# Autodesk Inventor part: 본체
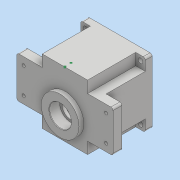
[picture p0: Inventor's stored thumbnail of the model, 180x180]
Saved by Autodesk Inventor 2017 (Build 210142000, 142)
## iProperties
Part Number: 본체
Material: 일반
Document SubType Name: Modeling
Designer: user
Density: 1 g/cm^3
Appearance: 기본값
Author: user
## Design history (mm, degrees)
sketch "스케치1"
  geometry: L1 (0, -94)-(-33, -94); L2 (-33, -94)-(-33, -77); L3 (-33, -77)-(-70, -77); L4 (-70, -77)-(-70, -17); L5 (-70, -17)-(-33, -17); L6 (-33, -17)-(-33, 0); L7 (-33, 0)-(0, 0); L8 (0, -94)-(0, 0); L9 (0, -94)-(33, -94); L10 (33, -94)-(33, -77); L11 (33, -77)-(70, -77); L12 (70, -77)-(70, -17); L13 (70, -17)-(33, -17); L14 (33, -17)-(33, 0); L15 (33, 0)-(0, 0)
  constraints: 30 end point, 6 perpendicular, 6 symmetric about line, 2 horizontal
  dimensions: "d0" = 94 distance between parallel lines of L7 L1; "d1" = 33 distance from line of L7.end L2; "d2" = 70 distance from line of L7.end L4; "d3" = 33 distance from line of L7.end L6; "d4" = 60 distance between parallel lines of L5 L3; "d5" = 17 distance between parallel lines of L3 L1
extrude "돌출1" new body sketch "스케치1" distance "d6" = 13; taper "d7" = 0 deg
sketch "스케치3"
  geometry: L1 (-33, 0)-(33, 0) reference; L2 (33, 94)-(-33, 94) reference; L3 (-33, 94)-(33, 94); L4 (33, 77)-(33, 94) reference; L5 (33, 94)-(33, 77); L6 (33, 77)-(47, 77); L7 (70, 77)-(33, 77) reference; L8 (47, 77)-(47, 17); L9 (33, 17)-(70, 17) reference; L10 (33, 17)-(33, 0); L11 (33, 0)-(0, 0); L12 (-33, 17)-(-33, 0) reference; L13 (-33, 0)-(-33, 17); L14 (-33, 17)-(-47, 17); L15 (-70, 17)-(-33, 17) reference; L16 (-33, 77)-(-70, 77) reference; L17 (-47, 77)-(-33, 77); L18 (-33, 94)-(-33, 77) reference; L19 (-33, 77)-(-33, 94); L20 (-47, 77)-(-47, 17); L21 (0, 0)-(-33, 0); L22 (47, 17)-(33, 17)
  constraints: 26 end point, 4 collinear, 3 perpendicular, 3 point on line, 3 vertical, 1 horizontal
  dimensions: "d13" = 47 horizontal distance of L6.end L11.end; "d15" = 47 distance from line of L20 L11.end
extrude "돌출3" join sketch "스케치3" distance "d16" = 57; taper "d17" = 0 deg
sketch "스케치4"
  geometry: L1 (-47, 94)-(47, 94); L2 (47, 94)-(47, 0); L3 (47, 0)-(-47, 0); L4 (-47, 0)-(-47, 94); L5 (33, 94)-(-33, 94) reference; 2 further points
  constraints: 8 end point, 2 midpoint, 2 parallel, 1 horizontal, 1 perpendicular
  dimensions: "d18" = 94 distance of L2.end L3.end; "d19" = 94 distance of L1.end L2.end; "d20" = 47 distance from line of L4 point (0, 0)
extrude "돌출4" join sketch "스케치4" distance "d21" = 10; taper "d22" = 0 deg
sketch "스케치6"
  geometry: L1 (47, 94)-(-47, 94) reference; L2 (-47, 94)-(-47, 0) reference; C1 r 3.5 at (-40, 87); 1 further point
  constraints: 1 centre point
  dimensions: "d27" = 7 diameter of C1; "d28" = 7 distance from line of L1 C1.centre; "d29" = 7 distance from line of L2 C1.centre
extrude "돌출5" cut sketch "스케치6" distance "d30" = 30; taper "d31" = 0 deg
sketch "스케치8"
  geometry: 1 further point
sketch "스케치11"
  geometry: L1 (47, 94)-(-47, 94) reference; L2 (-47, 0)-(47, 0) reference; C1 r 43 at (0, 47); 2 further points
  constraints: 1 centre point, 1 midpoint, 1 vertical alignment
  dimensions: "d51" = 86 diameter of C1; "d52" = 47 distance from line of L1 C1.centre
extrude "돌출9" cut sketch "스케치11" distance "d53" = 9; taper "d54" = 0 deg
sketch "스케치12"
  geometry: C1 r 40 at (0, 0); C2 r 43 at (0, 0) reference; 1 further point
  constraints: 1 centre point, 1 concentric
  dimensions: "d55" = 80 diameter of C1
extrude "돌출10" cut sketch "스케치12" distance "d56" = 62; taper "d57" = 0 deg
sketch "스케치13"
  geometry: 1 further point
sketch "스케치14"
  geometry: C1 r 21 at (0, 11); C2 r 15 at (0, -20); C3 r 40 at (0, 0) reference; 1 further point
  constraints: 2 centre point, 2 vertical alignment
  dimensions: "d58" = 42 diameter of C1; "d59" = 30 diameter of C2; "d60" = 11 distance of C3.centre C1.centre; "d61" = 20 distance of C2.centre C3.centre
extrude "돌출11" join sketch "스케치14" distance "d62" = 7; taper "d63" = 0 deg
sketch "스케치15"
  geometry: L1 (-33, 0)-(33, 0) reference; L2 (-33, -17)-(-33, 0) reference; L3 (-70, -17)-(-33, -17) reference; L4 (-70, -77)-(-70, -17) reference; L5 (-33, -77)-(-70, -77) reference; L6 (-33, -94)-(-33, -77) reference; L7 (33, -94)-(-33, -94) reference; L8 (33, -77)-(33, -94) reference; L9 (70, -77)-(33, -77) reference; L10 (70, -17)-(70, -77) reference; L11 (33, -17)-(70, -17) reference; L12 (33, 0)-(33, -17) reference; C1 r 16 at (0, -58); C2 r 40 at (0, -47) reference; 1 further point
  constraints: 1 centre point, 1 vertical alignment
  dimensions: "d64" = 32 diameter of C1; "d65" = 11 distance of C2.centre C1.centre
extrude "돌출12" cut sketch "스케치15" distance "d66" = 8.3; taper "d67" = 0 deg
sketch "스케치16"
  geometry: C1 r 12.5 at (0, 0); C2 r 16 at (0, 0) reference; 1 further point
  constraints: 1 centre point, 1 concentric
  dimensions: "d68" = 25 diameter of C1
extrude "돌출13" cut sketch "스케치16" distance "d69" = 4.7; taper "d70" = 0 deg
sketch "스케치17"
  geometry: L1 (47, -19)-(47, 41) reference; C1 r 17.5 at (0, 0); A1 r 21 centre (0, 0) between (-8.978, 18.984) and (8.978, 18.984) reference; 1 further point
  constraints: 1 centre point, 1 concentric
  dimensions: "d71" = 35 diameter of C1
extrude "돌출14" cut sketch "스케치17" distance "d72" = 10; taper "d73" = 0 deg
sketch "스케치18"
  geometry: C1 r 11 at (0, -20); A1 r 15 centre (0, -20) between (-8.978, -7.984) and (8.978, -7.984) reference; 1 further point
  constraints: 1 centre point, 1 concentric
  dimensions: "d74" = 22 diameter of C1
extrude "돌출15" cut sketch "스케치18" distance "d75" = 7; taper "d76" = 0 deg
sketch "스케치19"
  geometry: C1 r 9.5 at (0, 0); C2 r 11 at (0, 0) reference; 1 further point
  constraints: 1 centre point, 1 concentric
  dimensions: "d77" = 19 diameter of C1
extrude "돌출16" cut sketch "스케치19" distance "d78" = 3; taper "d79" = 0 deg
sketch "스케치20"
  geometry: L1 (-14, 80)-(80, 80) reference; L2 (0, 0)-(66, 0) reference; 3 further points
  constraints: 1 midpoint, 1 vertical alignment, 1 other
  dimensions: "d81" = 40 distance from line of L1 point (33, 40)
feature "엠보싱2" sketch "스케치20" dims "d0" = 94, "d1" = 33, "d2" = 70, "d3" = 33, "d4" = 60, "d5" = 17, "d82" = 0.5, "d83" = 0
sketch "스케치21"
  geometry: C1 r 27.5 at (0, -58); C2 r 16 at (0, -58) reference; 1 further point
  constraints: 1 centre point, 1 concentric
  dimensions: "d84" = 55 diameter of C1
extrude "돌출17" join sketch "스케치21" distance "d85" = 7; taper "d86" = 0 deg
sketch "스케치22"
  geometry: L1 (-47, 0)-(47, 0) reference; L2 (70, 17)-(70, 77) reference; L3 (47, 17)-(70, 17) reference; 2 further points
  dimensions: "d88" = 10 distance from line of L2 point (60, 28); "d89" = 11 distance from line of point (60, 28) L3
hole "구멍1" sketch "스케치22" at (60, 28) diameter "d90" = 4.5; stored, may be unused: countersink angle "d94" = 90 deg, drill point angle "d96" = 0 deg; dims "d91" = 6, "d92" = 10, "d93" = 5, "d95" = 8
sketch "스케치24"
  geometry: A1 r 40 centre (0, 0) between (39.279, -7.559) and (39.279, 7.559) reference; A2 r 4 centre (36, 0) between (36.19, 3.995) and (36.19, -3.995); A3 r 3 centre (36.333, -6.992) between (39.279, -7.559) and (36.19, -3.995); A4 r 3 centre (36.333, 6.992) between (36.19, 3.995) and (39.279, 7.559); 1 further point
  constraints: 8 point on circle, 4 tangent, 3 centre point, 1 horizontal alignment
  dimensions: "d101" = 8 diameter of A2; "d102" = 36 distance of A2.centre A1.centre; "d103" = 3 radius of A3; "d104" = 3 radius of A4
extrude "돌출18" join sketch "스케치24" stored distance "d105" = 7; taper "d106" = 0 deg
sketch "스케치25"
  geometry: C1 r 43 at (0, 0) reference; A1 r 40 centre (0, 0) between (39.279, 7.559) and (39.279, -7.559) reference; A2 r 3 centre (36.333, 6.992) between (36.19, 3.995) and (39.279, 7.559) reference; A3 r 4 centre (36, 0) between (36.19, 3.995) and (36.19, -3.995) reference; A4 r 3 centre (36.333, -6.992) between (39.279, -7.559) and (36.19, -3.995) reference; 2 further points
  constraints: 1 coincident
hole "구멍2" sketch "스케치25" at (36, 0) diameter "d107" = 3.242; stored, may be unused: countersink angle "d111" = 82 deg, drill point angle "d113" = 118 deg; dims "d108" = 7, "d109" = 3.023, "d110" = 5, "d112" = 9
fillet "모깎기1" dims "d120" = 3
chamfer "모따기1" distance "d121" = 0.8; stored, may be unused: second distance "d122" = 2, angle "d123" = 30 deg
chamfer "모따기2" distance "d124" = 1; stored, may be unused: second distance "d125" = 2, angle "d126" = 30 deg
fillet "모깎기2" dims "d127" = 3
fillet "모깎기3" dims "d128" = 3
node "솔리드1"
pattern_linear "직사각형 패턴1" dims "d34" = 80, "d37" = 80
mirror "미러1"
pattern_linear "직사각형 패턴2" dims "d116" = 120, "d119" = 38
node "투영된 루프3"
node "투영된 루프4"
node "투영된 루프5"
